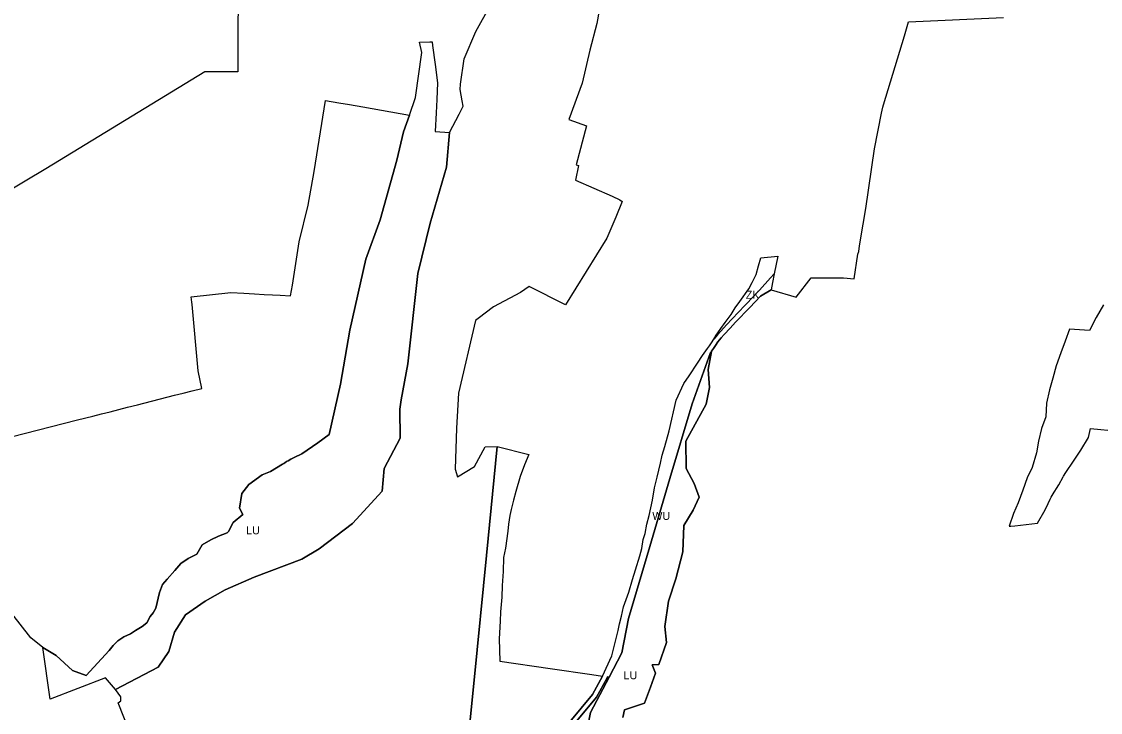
# Model space of a CAD drawing. Extents: x -532067 to -529270, y -1180561 to -1176456.
# Drawn here: x -531385 to -530711, y -1178985 to -1178554 of the extents above; entities that cross this region are included whole.
import ezdxf

# ---------------------------------------------------------------- set-up
doc = ezdxf.new("R2010")
doc.units = 0
for name, color, linetype in [('90630013', 7, 'Continuous'), ('90710013', 7, 'Continuous'), ('90750013', 7, 'Continuous'), ('90770013', 7, 'Continuous')]:
    doc.layers.add(name, color=color, linetype=linetype)

msp = doc.modelspace()

# ---------------------------------------------------------------- linework, layer by layer
at = {"layer": '90630013'}
msp.add_lwpolyline([(-531042.2433, -1178991.17145), (-531027.9663, -1178974.07545), (-531021.8043, -1178962.73745), (-531015.9713, -1178949.92945), (-531013.4493, -1178939.96745), (-531012.0303, -1178934.27445), (-531011.2423, -1178930.00545), (-531010.0433, -1178925.18545), (-531008.6523, -1178919.43145), (-531005.3493, -1178910.36345), (-531003.0893, -1178902.34145), (-531001.2443, -1178896.29745), (-530998.5813, -1178887.58045), (-530997.1793, -1178883.08045), (-530996.3383, -1178877.45645), (-530995.0763, -1178873.66045), (-530994.1893, -1178867.85645), (-530992.7503, -1178862.40445), (-530990.5123, -1178852.78245), (-530989.3023, -1178845.04245), (-530987.6053, -1178838.57645), (-530986.7013, -1178834.03845), (-530985.6833, -1178829.72745), (-530984.5523, -1178824.84945), (-530982.8233, -1178819.33645), (-530980.2493, -1178809.61445), (-530975.7063, -1178790.32345), (-530971.0113, -1178779.99345), (-530967.6793, -1178775.28445), (-530962.5353, -1178767.33545), (-530959.2563, -1178762.51945), (-530956.2123, -1178758.17345), (-530954.9823, -1178756.41145), (-530953.7523, -1178754.64945), (-530952.2533, -1178752.26245), (-530949.9443, -1178749.61245), (-530947.9783, -1178747.35145), (-530944.2853, -1178743.36545), (-530940.8443, -1178739.65145), (-530940.7283, -1178739.53145), (-530932.8293, -1178731.36045), (-530931.9773, -1178730.47945), (-530923.6813, -1178721.74945), (-530916.9473, -1178713.99645), (-530914.5073, -1178711.44845), (-530915.6033, -1178717.02345), (-530916.4713, -1178721.44245), (-530923.0293, -1178725.41845), (-530929.8113, -1178732.55545), (-530938.6653, -1178741.71345), (-530942.0843, -1178745.40445), (-530945.7453, -1178749.35545), (-530947.6813, -1178751.58245), (-530949.8373, -1178754.05645), (-530951.2503, -1178756.30645), (-530952.5223, -1178758.12845), (-530953.7533, -1178759.89245), (-530953.8033, -1178759.96445), (-530954.3173, -1178760.69845), (-530965.7473, -1178792.63645), (-530979.6933, -1178839.26645), (-530992.1863, -1178881.81545), (-531005.5503, -1178926.69545), (-531009.6953, -1178948.12645), (-531017.7253, -1178963.35045), (-531018.7193, -1178963.20145), (-531019.1183, -1178964.07745), (-531025.4723, -1178975.76945), (-531039.9043, -1178993.05145)], dxfattribs=at)
at = {"layer": '90710013'}
for points in [[(-530949.9443, -1178749.61245), (-530952.2533, -1178752.26245), (-530950.7543, -1178749.87545), (-530947.9163, -1178745.74545), (-530945.2193, -1178741.90145), (-530941.5283, -1178736.91745), (-530938.9733, -1178732.78845), (-530936.1343, -1178728.80145), (-530930.5123, -1178720.97745), (-530928.2813, -1178716.97945), (-530925.8903, -1178712.02245), (-530924.2963, -1178706.58645), (-530922.8613, -1178701.46945), (-530912.3603, -1178700.52045), (-530914.5073, -1178711.44845), (-530916.9473, -1178713.99645), (-530923.6813, -1178721.74945), (-530931.9773, -1178730.47945), (-530932.8293, -1178731.36045), (-530940.7283, -1178739.53145), (-530940.8443, -1178739.65145), (-530944.2853, -1178743.36545), (-530947.9783, -1178747.35145)], [(-531045.6303, -1179041.61945), (-531062.1193, -1179050.21345), (-531061.5003, -1179041.71745), (-531058.6293, -1179028.66145), (-531053.9213, -1179014.79845), (-531048.2503, -1179003.84145), (-531039.9043, -1178993.05145), (-531025.4723, -1178975.76945), (-531019.1183, -1178964.07745), (-531018.7193, -1178963.20145), (-531017.7253, -1178963.35045), (-531029.3253, -1178985.34245), (-531036.2273, -1179019.31245)]]:
    msp.add_lwpolyline(points, close=True, dxfattribs=at)
msp.add_lwpolyline([(-531105.1903, -1178996.29345), (-531102.0663, -1178965.19545), (-531094.2443, -1178887.32545), (-531087.5073, -1178819.36745), (-531067.8833, -1178824.35045), (-531070.5033, -1178830.74845), (-531073.3233, -1178838.02945), (-531076.0403, -1178847.33045), (-531077.4793, -1178852.78245), (-531078.9003, -1178858.75645), (-531079.6013, -1178862.41145), (-531080.4423, -1178867.89545), (-531081.0033, -1178872.25445), (-531082.4043, -1178882.79945), (-531083.5793, -1178888.56545), (-531083.7533, -1178897.45945), (-531084.4483, -1178906.17845), (-531084.6223, -1178913.32745), (-531085.0203, -1178917.98745), (-531085.4933, -1178922.57245), (-531085.8083, -1178928.42345), (-531086.2813, -1178939.33445), (-531085.9663, -1178953.25045), (-531054.4373, -1178957.83545), (-531028.5233, -1178961.72845), (-531021.8043, -1178962.73745), (-531027.9663, -1178974.07545), (-531042.2433, -1178991.17145)], dxfattribs=at)
at = {"layer": '90750013'}
for points in [[(-531389.0103, -1178482.84145), (-531378.5853, -1178483.63045), (-531367.9633, -1178484.61645), (-531356.9493, -1178486.19545), (-531347.3113, -1178486.98445), (-531337.4763, -1178488.36545), (-531326.6383, -1178489.54945), (-531315.2303, -1178493.49545), (-531311.2963, -1178494.87645), (-531305.7883, -1178496.65245), (-531295.3633, -1178500.00645), (-531278.2513, -1178505.72745), (-531272.6023, -1178507.61445), (-531262.2153, -1178511.21345), (-531249.3723, -1178515.57045), (-531249.6513, -1178585.37145), (-531270.2833, -1178585.45145), (-531369.5513, -1178646.02645), (-531423.3123, -1178678.04545)], [(-531021.8373, -1178535.28245), (-531025.3933, -1178555.25445), (-531029.6223, -1178571.87245), (-531034.5563, -1178592.53945), (-531042.8453, -1178615.18345), (-531031.7993, -1178619.22745), (-531038.2763, -1178643.59045), (-531036.8373, -1178643.95145), (-531038.6363, -1178653.15445), (-531015.6983, -1178663.10845), (-531010.8983, -1178665.28345), (-531009.4903, -1178666.32845), (-531013.4493, -1178676.07445), (-531019.2063, -1178689.24845), (-531044.8463, -1178730.84945), (-531067.6733, -1178719.51645), (-531073.0833, -1178723.27445), (-531089.9533, -1178732.07445), (-531099.4733, -1178739.37345), (-531101.2093, -1178740.76645), (-531111.8013, -1178786.05245), (-531112.9943, -1178807.99345), (-531113.8903, -1178833.51745), (-531112.3983, -1178838.32845), (-531101.7303, -1178831.75845), (-531095.0083, -1178819.57145), (-531087.5073, -1178819.36745), (-531094.2443, -1178887.32545), (-531102.0663, -1178965.19545), (-531105.1903, -1178996.29345)], [(-531304.2533, -1179029.90345), (-531324.3793, -1178979.33545), (-531322.5833, -1178978.13445), (-531322.5833, -1178975.53145), (-531325.9763, -1178971.12745), (-531299.2783, -1178957.06645), (-531292.6923, -1178947.40245), (-531289.1553, -1178935.29145), (-531282.1923, -1178924.49745), (-531269.9693, -1178915.80345), (-531257.5243, -1178908.89345), (-531239.3013, -1178900.86845), (-531209.5223, -1178889.72245), (-531198.8553, -1178883.25845), (-531177.9653, -1178867.43145), (-531159.5203, -1178847.14545), (-531158.1723, -1178833.07245), (-531148.1973, -1178814.06145), (-531148.4183, -1178796.05045), (-531147.6043, -1178790.15645), (-531143.3673, -1178767.76145), (-531137.2273, -1178711.43445), (-531129.5003, -1178679.88945), (-531119.2563, -1178644.91845), (-531117.4553, -1178623.21045), (-531111.4003, -1178611.77845), (-531108.9063, -1178606.89545), (-531109.5003, -1178603.44145), (-531110.6873, -1178596.41545), (-531110.5683, -1178593.08045), (-531108.3133, -1178577.24145), (-531100.9953, -1178560.31245), (-531091.7233, -1178543.75345)], [(-531009.0323, -1178988.45645), (-531008.1043, -1178983.80445), (-530995.4923, -1178979.52545), (-530991.7833, -1178969.47845), (-530988.6303, -1178960.91945), (-530990.8563, -1178955.71045), (-530986.5903, -1178955.52445), (-530981.8163, -1178941.61045), (-530982.8893, -1178931.64945), (-530980.5643, -1178915.91245), (-530975.9163, -1178901.92345), (-530971.5583, -1178885.01945), (-530970.9773, -1178868.69945), (-530965.1663, -1178859.08245), (-530961.3893, -1178850.92245), (-530964.5853, -1178842.47145), (-530969.5243, -1178833.14545), (-530969.8153, -1178815.95145), (-530957.0313, -1178792.92845), (-530954.9973, -1178782.43645), (-530955.8693, -1178771.36245), (-530953.8033, -1178759.96445), (-530953.7533, -1178759.89245), (-530952.5223, -1178758.12845), (-530951.2503, -1178756.30645), (-530949.8373, -1178754.05645), (-530947.6813, -1178751.58245), (-530945.7453, -1178749.35545), (-530942.0843, -1178745.40445), (-530938.6653, -1178741.71345), (-530929.8113, -1178732.55545), (-530923.0293, -1178725.41845), (-530916.4713, -1178721.44245), (-530900.7903, -1178726.01145), (-530891.5813, -1178714.01945), (-530871.3873, -1178714.01945), (-530864.6503, -1178714.66545), (-530862.2713, -1178699.29845), (-530861.8153, -1178697.61845), (-530861.2243, -1178694.06745), (-530858.9833, -1178680.59145), (-530857.3583, -1178670.82045), (-530851.9283, -1178633.59945), (-530847.4513, -1178611.31245), (-530846.6633, -1178607.38845), (-530846.3793, -1178605.97445), (-530834.6973, -1178567.65645), (-530833.2853, -1178563.02545), (-530830.6193, -1178554.28145), (-530771.3363, -1178551.46545)], [(-531391.1593, -1178813.33445), (-531349.6163, -1178802.76845), (-531340.0663, -1178800.33945), (-531334.6303, -1178798.95745), (-531329.3683, -1178797.61945), (-531323.8563, -1178796.21745), (-531318.3873, -1178794.82645), (-531312.3013, -1178793.27845), (-531289.0893, -1178787.37445), (-531283.7113, -1178786.00645), (-531278.0623, -1178784.56945), (-531272.1543, -1178783.06645), (-531274.2653, -1178772.10845), (-531278.1913, -1178730.75445), (-531278.3513, -1178729.31045), (-531278.7223, -1178725.96645), (-531253.8883, -1178723.20845), (-531245.7973, -1178723.66845), (-531239.0753, -1178724.05045), (-531233.1523, -1178724.38745), (-531228.0093, -1178724.67945), (-531223.2003, -1178724.95345), (-531216.6163, -1178725.32745), (-531215.4103, -1178718.60345), (-531211.1943, -1178691.48345), (-531205.6053, -1178668.57345), (-531201.9613, -1178647.61445), (-531194.7893, -1178603.26845), (-531186.5583, -1178604.71045), (-531179.9263, -1178605.87245), (-531171.4123, -1178607.36345), (-531142.4333, -1178612.43845), (-531146.0613, -1178622.99245), (-531150.3113, -1178640.60245), (-531160.7483, -1178677.84845), (-531169.5973, -1178702.41145), (-531179.6803, -1178746.78945), (-531185.4403, -1178780.39845), (-531192.4373, -1178811.77845), (-531199.6413, -1178817.14645), (-531209.5043, -1178823.95445), (-531214.4923, -1178826.12245), (-531216.4873, -1178827.28945), (-531218.1643, -1178828.29445), (-531219.1933, -1178828.70745), (-531220.2223, -1178829.53345), (-531220.8213, -1178829.91945), (-531221.6633, -1178830.35845), (-531229.1463, -1178835.00945), (-531234.4423, -1178836.98645), (-531242.7183, -1178843.11345), (-531247.0533, -1178848.64845), (-531248.4323, -1178857.93745), (-531246.4623, -1178861.89045), (-531252.5703, -1178866.83245), (-531255.3293, -1178872.36645), (-531256.3143, -1178873.15745), (-531261.6343, -1178875.33145), (-531266.4963, -1178877.62645), (-531271.8193, -1178880.77545), (-531275.0953, -1178886.52545), (-531280.5543, -1178889.26345), (-531285.1953, -1178892.41245), (-531289.0173, -1178896.65745), (-531293.6583, -1178902.13345), (-531296.5243, -1178905.55645), (-531298.4353, -1178910.48545), (-531300.7553, -1178920.34245), (-531302.5303, -1178923.08145), (-531304.3043, -1178925.40845), (-531306.4883, -1178929.37945), (-531309.3543, -1178931.70645), (-531313.4493, -1178934.30745), (-531316.5883, -1178936.36145), (-531320.6833, -1178938.14145), (-531324.5053, -1178940.74245), (-531327.3713, -1178943.61745), (-531329.9643, -1178946.62945), (-531344.4013, -1178962.20445), (-531352.9383, -1178959.14645), (-531362.9383, -1178949.72645), (-531371.2753, -1178944.90345), (-531378.8583, -1178938.69745), (-531402.8043, -1178908.46945)], [(-530708.8873, -1178730.85145), (-530713.5373, -1178738.81945), (-530717.5863, -1178746.82345), (-530730.1623, -1178745.99845), (-530732.9033, -1178753.56045), (-530735.6443, -1178760.94945), (-530738.3863, -1178769.02645), (-530740.6133, -1178776.58845), (-530742.6203, -1178784.04045), (-530744.6043, -1178792.23545), (-530744.9543, -1178800.78245), (-530747.6393, -1178808.15745), (-530749.5063, -1178816.00145), (-530750.7903, -1178823.26045), (-530753.4283, -1178832.35745), (-530756.5093, -1178838.87745), (-530759.3103, -1178846.60445), (-530762.2283, -1178854.44745), (-530765.0293, -1178861.12145), (-530767.8303, -1178869.08245), (-530766.7803, -1178869.08245), (-530764.3293, -1178868.96545), (-530750.2063, -1178867.20945), (-530745.4213, -1178858.77945), (-530743.4653, -1178854.85445), (-530742.1833, -1178852.28245), (-530741.5703, -1178851.05245), (-530739.6273, -1178847.83645), (-530739.2363, -1178847.18845), (-530738.2523, -1178845.56045), (-530736.9013, -1178843.32545), (-530734.0183, -1178838.22545), (-530733.7853, -1178837.81445), (-530732.4663, -1178835.48145), (-530727.5643, -1178828.57445), (-530723.0553, -1178821.56445), (-530718.2813, -1178813.61845), (-530717.0633, -1178808.11745), (-530561.4833, -1178823.02345)]]:
    msp.add_lwpolyline(points, dxfattribs=at)
at = {"layer": '90770013'}
msp.add_lwpolyline([(-531299.2783, -1178957.06645), (-531325.9763, -1178971.12745), (-531332.1623, -1178963.72045), (-531366.8853, -1178977.13345), (-531371.2753, -1178944.90345), (-531362.9383, -1178949.72645), (-531352.9383, -1178959.14645), (-531344.4013, -1178962.20445), (-531329.9643, -1178946.62945), (-531327.3713, -1178943.61745), (-531324.5053, -1178940.74245), (-531320.6833, -1178938.14145), (-531316.5883, -1178936.36145), (-531313.4493, -1178934.30745), (-531309.3543, -1178931.70645), (-531306.4883, -1178929.37945), (-531304.3043, -1178925.40845), (-531302.5303, -1178923.08145), (-531300.7553, -1178920.34245), (-531298.4353, -1178910.48545), (-531296.5243, -1178905.55645), (-531293.6583, -1178902.13345), (-531289.0173, -1178896.65745), (-531285.1953, -1178892.41245), (-531280.5543, -1178889.26345), (-531275.0953, -1178886.52545), (-531271.8193, -1178880.77545), (-531266.4963, -1178877.62645), (-531261.6343, -1178875.33145), (-531256.3143, -1178873.15745), (-531255.3293, -1178872.36645), (-531252.5703, -1178866.83245), (-531246.4623, -1178861.89045), (-531248.4323, -1178857.93745), (-531247.0533, -1178848.64845), (-531242.7183, -1178843.11345), (-531234.4423, -1178836.98645), (-531229.1463, -1178835.00945), (-531221.6633, -1178830.35845), (-531220.8213, -1178829.91945), (-531220.2223, -1178829.53345), (-531219.1933, -1178828.70745), (-531218.1643, -1178828.29445), (-531216.4873, -1178827.28945), (-531214.4923, -1178826.12245), (-531209.5043, -1178823.95445), (-531199.6413, -1178817.14645), (-531192.4373, -1178811.77845), (-531185.4403, -1178780.39845), (-531179.6803, -1178746.78945), (-531169.5973, -1178702.41145), (-531160.7483, -1178677.84845), (-531150.3113, -1178640.60245), (-531146.0613, -1178622.99245), (-531142.4333, -1178612.43845), (-531138.6693, -1178601.49045), (-531134.6043, -1178573.31445), (-531136.0823, -1178567.01245), (-531129.5653, -1178566.64245), (-531128.1403, -1178566.76145), (-531127.9973, -1178569.06245), (-531126.3883, -1178580.95545), (-531124.9353, -1178592.24745), (-531125.2913, -1178602.60845), (-531125.7663, -1178610.94445), (-531126.2593, -1178622.60045), (-531117.4553, -1178623.21045), (-531119.2563, -1178644.91845), (-531129.5003, -1178679.88945), (-531137.2273, -1178711.43445), (-531143.3673, -1178767.76145), (-531147.6043, -1178790.15645), (-531148.4183, -1178796.05045), (-531148.1973, -1178814.06145), (-531158.1723, -1178833.07245), (-531159.5203, -1178847.14545), (-531177.9653, -1178867.43145), (-531198.8553, -1178883.25845), (-531209.5223, -1178889.72245), (-531239.3013, -1178900.86845), (-531257.5243, -1178908.89345), (-531269.9693, -1178915.80345), (-531282.1923, -1178924.49745), (-531289.1553, -1178935.29145), (-531292.6923, -1178947.40245)], close=True, dxfattribs=at)
msp.add_lwpolyline([(-531036.2273, -1179019.31245), (-531029.3253, -1178985.34245), (-531017.7253, -1178963.35045), (-531009.6953, -1178948.12645), (-531005.5503, -1178926.69545), (-530992.1863, -1178881.81545), (-530979.6933, -1178839.26645), (-530965.7473, -1178792.63645), (-530954.3173, -1178760.69845), (-530953.8033, -1178759.96445), (-530955.8693, -1178771.36245), (-530954.9973, -1178782.43645), (-530957.0313, -1178792.92845), (-530969.8153, -1178815.95145), (-530969.5243, -1178833.14545), (-530964.5853, -1178842.47145), (-530961.3893, -1178850.92245), (-530965.1663, -1178859.08245), (-530970.9773, -1178868.69945), (-530971.5583, -1178885.01945), (-530975.9163, -1178901.92345), (-530980.5643, -1178915.91245), (-530982.8893, -1178931.64945), (-530981.8163, -1178941.61045), (-530986.5903, -1178955.52445), (-530990.8563, -1178955.71045), (-530988.6303, -1178960.91945), (-530991.7833, -1178969.47845), (-530995.4923, -1178979.52545), (-531008.1043, -1178983.80445), (-531009.0323, -1178988.45645)], dxfattribs=at)

# ---------------------------------------------------------------- texts
at = {"layer": '90630013'}
msp.add_text('WU', height=5, rotation=0.00000001, dxfattribs=at).set_placement((-530990.6978, -1178865.16293))
at = {"layer": '90710013'}
msp.add_text('ZK', height=5, rotation=359.99999997, dxfattribs=at).set_placement((-530932.3068, -1178727.14749))
at = {"layer": '90770013'}
for rotation, p in [(0.00000001, (-531244.3653, -1178874.15744)), (0.00000004, (-531008.6533, -1178964.64776))]:
    msp.add_text('LU', height=5, rotation=rotation, dxfattribs=at).set_placement(p)

doc.saveas('drawing.dxf')
